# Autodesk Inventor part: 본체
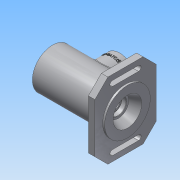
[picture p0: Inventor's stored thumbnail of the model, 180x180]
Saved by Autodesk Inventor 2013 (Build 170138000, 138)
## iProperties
Created: 2017-10
Part Number: 본체
Material: 알루미늄 6061
Document SubType Name: Modeling
Designer: Administrator
Density: 2.71 g/cm^3
Mass: 740.515 g
Surface Area: 653.212 cm^2
Volume: 273.253 cm^3
Author: Administrator
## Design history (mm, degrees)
sketch "스케치1"
  geometry: L1 (0, 0)-(0, 31); L2 (101, 16)-(101, 12.904); L3 (101, 12.904)-(100.3, 12.5); L4 (100.3, 12.5)-(93.7, 12.5); L5 (93.7, 12.5)-(93.7, 10); L6 (93.7, 10)-(91, 10); L7 (91, 10)-(91, 16.5); L8 (91, 16.5)-(86, 16.5); L9 (86, 16.5)-(86, 17.5); L10 (86, 17.5)-(75, 17.5); L11 (75, 17.5)-(75, 26); L12 (75, 26)-(37, 26); L13 (37, 26)-(37, 17.5); L14 (37, 17.5)-(26, 17.5); L15 (26, 17.5)-(26, 18.5); L16 (26, 18.5)-(24.25, 18.5); L17 (24.25, 18.5)-(24.25, 17.5); L18 (24.25, 17.5)-(21, 17.5); L19 (21, 17.5)-(21, 20); L20 (21, 20)-(12, 20); L21 (12, 20)-(12, 24); L22 (12, 24)-(9, 24); L23 (9, 24)-(9, 0); L24 (9, 0)-(0, 0); L25 (9, 0)-(96.109, 0); L26 (115, 22)-(115, 35); L27 (115, 22)-(101, 16); L28 (0, 31)-(102, 31); L29 (102, 31)-(102, 35); L30 (102, 35)-(115, 35)
  constraints: 60 end point, 12 parallel, 3 perpendicular, 1 collinear, 1 vertical
  dimensions: "d3" = 40 diameter of L20 L25; "d4" = 48 diameter of L22 L25; "d5" = 35 diameter of L18 L25; "d6" = 37 diameter of L16 L25; "d7" = 1.75 distance of L15.end L16.end; "d8" = 35 diameter of L14 L25; "d9" = 52 diameter of L12 L25; "d10" = 35 diameter of L10 L25; "d11" = 33 diameter of L8 L25; "d12" = 20 diameter of L6 L25; "d13" = 25 diameter of L4 L25; "d14" = 2.7 distance of L5.end L6.end; "d16" = 7.3 distance between parallel lines of L2 L5; "d17" = 0.7 horizontal distance of L2.end L3.end; "d19" = 32 diameter of L2.start L25; "d23" = 12 distance between parallel lines of L21 L1; "d24" = 3 distance of L21.end L22.end; "d25" = 21 distance between parallel lines of L19 L1; "d26" = 26 distance between parallel lines of L15 L1; "d27" = 60 distance between parallel lines of L9 L15; "d28" = 115 distance between parallel lines of L1 L26; "d30" = 30 deg angle of L4 L3; "d31" = 44 diameter of L26.start L25; "d32" = 14 distance between parallel lines of L2 L26; "d33" = 13 distance of L29.end L26.end; "d34" = 70 diameter of L30 L25; "d35" = 38 distance of L11.end L12.end; "d36" = 87.10866 distance of L23.end L25.end; "d37" = 11 distance of L13.end L14.end; "d38" = 62 diameter of L28 L25
revolve "회전1" sketch "스케치1" stored, may be unused: angle "d39" = 90 deg
sketch "스케치2"
  geometry: L1 (-58, -47)-(58, -47); L2 (58, -47)-(58, 47); L3 (58, 47)-(-58, 47); L4 (-58, 47)-(-58, -47); C1 r 31 at (0, 0) reference; 3 further points
  constraints: 8 end point, 2 midpoint, 2 parallel, 1 horizontal, 1 horizontal alignment, 1 perpendicular, 1 vertical alignment
  dimensions: "d40" = 116 distance of L1.start L1.end; "d42" = 94 distance of L3.end L1.start
extrude "돌출1" join sketch "스케치2" distance "d43" = 10; taper "d44" = 0 deg
sketch "스케치3"
  geometry: L1 (-50, 20)-(-50, -20); L2 (-42, -20)-(-42, 20); A1 r 4 centre (-46, -20) between (-50, -20) and (-42, -20); A2 r 4 centre (-46, 20) between (-42, 20) and (-50, 20); 2 further points
  constraints: 4 end point, 4 point on circle, 4 tangent, 2 centre point, 1 horizontal alignment, 1 midpoint, 1 parallel, 1 vertical, 1 vertical alignment
  dimensions: "d45" = 46 horizontal distance of point (0, 0) A2.centre; "d46" = 4 radius of A2; "d47" = 40 distance of A1.centre A2.centre
extrude "돌출2" cut sketch "스케치3" stored distance "d48" = 10; taper "d49" = 0 deg
hole "구멍1" diameter "d52" = 40.376; stored, may be unused: countersink angle "d56" = 90 deg, drill point angle "d58" = 0 deg; dims "d53" = 6, "d54" = 4, "d55" = 2, "d57" = 9, "d90" = 10, "d91" = 10
node "작업 평면1"
sketch "스케치4"
  geometry: L1 (0, 31)-(0, -31) reference; C1 r 25 at (-56, 0); 1 further point
  constraints: 1 centre point
  dimensions: "d60" = 50 diameter of C1; "d76" = 56 distance from line of C1.centre L1
extrude "돌출3" join sketch "스케치4" stored distance "d62" = 10; taper "d63" = 0 deg
hole "구멍2" diameter "d66" = 32; stored, may be unused: countersink angle "d70" = 90 deg, drill point angle "d72" = 0 deg; dims "d64" = 10, "d65" = 10, "d67" = 6, "d68" = 4, "d69" = 2, "d71" = 9
node "작업 평면2"
sketch "스케치5"
  geometry: L1 (31, 47)-(81, 47) reference; L2 (0, -31)-(0, 31) reference; 2 further points
  constraints: 1 other
  dimensions: "d74" = 10 distance from line of point (56, 37) L1; "d75" = 56 distance from line of point (56, 37) L2
feature "엠보싱1" sketch "스케치5" dims "d26" = 26, "d77" = 0.5, "d78" = 0
sketch "스케치6"
  geometry: 5 further points
  constraints: 3 vertical alignment, 1 other
  dimensions: "d80" = 41 distance of point (0, -20.5) point (0, 20.5); "d82" = 20.5 distance of point (0, 20.5) point (0, 0)
hole "구멍3" sketch "스케치6" at (0, 20.5), (0, -20.5) diameter "d83" = 2.459; stored, may be unused: countersink angle "d87" = 90 deg, drill point angle "d89" = 118 deg; dims "d84" = 6, "d85" = 4, "d86" = 2, "d88" = 8
chamfer "모따기1" distance "d92" = 20; stored, may be unused: second distance "d93" = 2, angle "d94" = 45 deg
fillet "모깎기1" dims "d95" = 0.3
chamfer "모따기2" distance "d96" = 1; stored, may be unused: second distance "d97" = 2, angle "d98" = 45 deg
fillet "모깎기2" dims "d99" = 3
node "솔리드1"
mirror "대칭1"
other parameters: "d59" = 47, "d73" = 106.75
